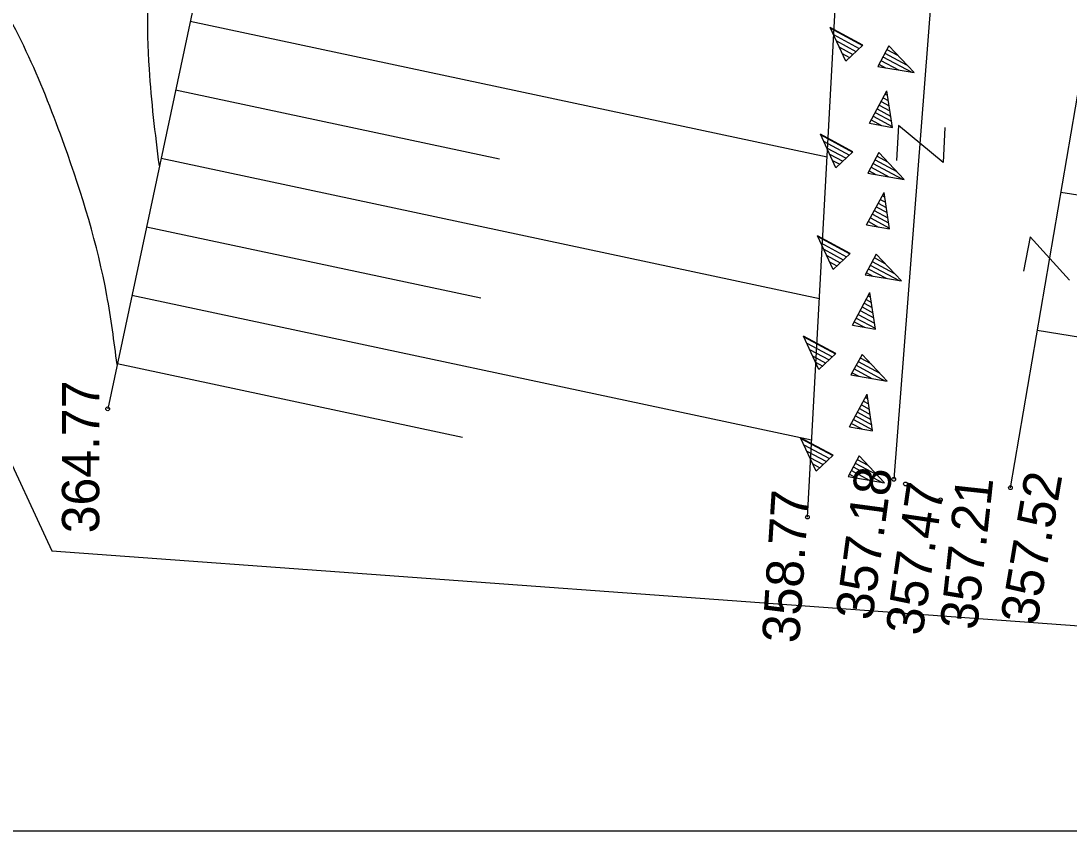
# Model space of a CAD drawing. Extents: x 4635329 to 4651863, y 5356628 to 5367582.
# Drawn here: x 4651179.57 to 4651202.03, y 5356627.73 to 5356645.09 of the extents above; entities that cross this region are included whole.
import ezdxf

# ---------------------------------------------------------------- set-up
doc = ezdxf.new("R2010")
doc.units = 0
for name, color, linetype in [('Level 1', 7, 'Continuous'), ('Level 13', 7, 'Continuous'), ('Level 44', 7, 'Continuous'), ('Level 45', 7, 'Continuous'), ('Level 46', 7, 'Continuous'), ('Level 48', 7, 'Continuous'), ('Level 49', 7, 'Continuous'), ('Level 50', 7, 'Continuous'), ('Level 53', 7, 'Continuous')]:
    doc.layers.add(name, color=color, linetype=linetype)

msp = doc.modelspace()

# ---------------------------------------------------------------- linework, layer by layer
at = {"layer": 'Level 1'}
for p, q in [((4651169.678, 5356656.408), (4651180.231, 5356633.731)), ((4651180.231, 5356633.731), (4651216.704, 5356631.078))]:
    msp.add_line(p, q, dxfattribs=at)
at = {"layer": 'Level 13'}
msp.add_lwpolyline([(4651092.18, 5356627.729), (4651092.18, 5356813.355), (4651331.195, 5356813.355), (4651331.195, 5356627.729)], close=True, dxfattribs=at)
at = {"layer": 'Level 44'}
for centre in [(4651181.425, 5356636.777), (4651198.275, 5356635.267), (4651198.525, 5356635.167), (4651200.775, 5356635.087), (4651199.275, 5356634.827), (4651196.425, 5356634.457)]:
    msp.add_circle(centre, 0.04, dxfattribs=at)
at = {"layer": 'Level 46'}
for points in [[(4651182.533, 5356641.982), (4651182.318, 5356644.059), (4651182.379, 5356646.848), (4651182.379, 5356648.849), (4651181.53, 5356650.244), (4651179.771, 5356652.002), (4651179.706, 5356652.031)], [(4651181.627, 5356637.725), (4651181.408, 5356639.209), (4651180.499, 5356642.422), (4651178.74, 5356646.121), (4651173.827, 5356650.062), (4651172.468, 5356650.413)]]:
    msp.add_spline(points, degree=3, dxfattribs=at)
at = {"layer": 'Level 48'}
for p, q in [((4651183.193, 5356645.083), (4651196.846, 5356642.176)), ((4651182.881, 5356643.616), (4651189.822, 5356642.138)), ((4651182.569, 5356642.149), (4651196.68, 5356639.144)), ((4651205.492, 5356640.832), (4651201.857, 5356641.413)), ((4651182.256, 5356640.681), (4651189.427, 5356639.155)), ((4651181.944, 5356639.214), (4651196.515, 5356636.112)), ((4651205.019, 5356637.869), (4651201.351, 5356638.456)), ((4651181.632, 5356637.747), (4651189.032, 5356636.172))]:
    msp.add_line(p, q, dxfattribs=at)
for points in [[(4651197.655, 5356677.577), (4651192.785, 5356671.627), (4651190.685, 5356664.357), (4651184.035, 5356649.037), (4651181.425, 5356636.777)], [(4651196.425, 5356634.457), (4651197.255, 5356649.677), (4651199.635, 5356666.497), (4651201.145, 5356666.267)]]:
    msp.add_lwpolyline(points, dxfattribs=at)
at = {"layer": 'Level 49'}
for p, q in [((4651197.61, 5356644.574), (4651196.913, 5356644.948)), ((4651197.246, 5356644.23), (4651196.913, 5356644.948)), ((4651196.919, 5356644.933), (4651197.602, 5356644.566)), ((4651196.983, 5356644.797), (4651197.533, 5356644.501)), ((4651197.046, 5356644.661), (4651197.464, 5356644.436)), ((4651197.61, 5356644.574), (4651197.246, 5356644.23)), ((4651197.109, 5356644.525), (4651197.395, 5356644.371)), ((4651197.172, 5356644.389), (4651197.326, 5356644.306)), ((4651198.168, 5356644.557), (4651197.932, 5356644.117)), ((4651198.085, 5356644.402), (4651198.55, 5356644.152)), ((4651198.128, 5356644.481), (4651198.355, 5356644.359)), ((4651198.711, 5356643.982), (4651198.168, 5356644.557)), ((4651197.235, 5356644.253), (4651197.257, 5356644.241)), ((4651197.957, 5356644.164), (4651198.1, 5356644.088)), ((4651198, 5356644.244), (4651198.38, 5356644.039)), ((4651198.042, 5356644.323), (4651198.661, 5356643.991)), ((4651197.932, 5356644.117), (4651198.711, 5356643.982)), ((4651197.752, 5356642.896), (4651198.126, 5356643.592)), ((4651198.089, 5356643.523), (4651198.14, 5356643.496)), ((4651198.245, 5356642.809), (4651198.126, 5356643.592)), ((4651197.962, 5356643.285), (4651198.191, 5356643.162)), ((4651198.004, 5356643.365), (4651198.175, 5356643.273)), ((4651198.047, 5356643.444), (4651198.158, 5356643.384)), ((4651197.834, 5356643.047), (4651198.243, 5356642.828)), ((4651197.876, 5356643.127), (4651198.225, 5356642.939)), ((4651197.919, 5356643.206), (4651198.208, 5356643.051)), ((4651197.752, 5356642.896), (4651198.245, 5356642.809)), ((4651197.791, 5356642.968), (4651198.011, 5356642.85)), ((4651197.399, 5356642.287), (4651196.702, 5356642.661)), ((4651197.035, 5356641.943), (4651196.702, 5356642.661)), ((4651196.709, 5356642.646), (4651197.392, 5356642.279)), ((4651196.772, 5356642.51), (4651197.323, 5356642.214)), ((4651196.835, 5356642.374), (4651197.254, 5356642.149)), ((4651196.898, 5356642.238), (4651197.185, 5356642.084)), ((4651196.961, 5356642.102), (4651197.116, 5356642.019)), ((4651197.399, 5356642.287), (4651197.035, 5356641.943)), ((4651197.958, 5356642.27), (4651197.721, 5356641.83)), ((4651197.874, 5356642.115), (4651198.34, 5356641.865)), ((4651197.917, 5356642.194), (4651198.144, 5356642.072)), ((4651198.5, 5356641.695), (4651197.958, 5356642.27)), ((4651197.025, 5356641.966), (4651197.047, 5356641.954)), ((4651197.747, 5356641.877), (4651197.889, 5356641.801)), ((4651197.789, 5356641.957), (4651198.17, 5356641.752)), ((4651197.832, 5356642.036), (4651198.45, 5356641.704)), ((4651197.721, 5356641.83), (4651198.5, 5356641.695)), ((4651197.692, 5356640.718), (4651198.066, 5356641.414)), ((4651197.986, 5356641.266), (4651198.097, 5356641.207)), ((4651198.029, 5356641.345), (4651198.08, 5356641.318)), ((4651198.185, 5356640.632), (4651198.066, 5356641.414)), ((4651197.858, 5356641.028), (4651198.147, 5356640.873)), ((4651197.901, 5356641.108), (4651198.131, 5356640.984)), ((4651197.944, 5356641.187), (4651198.115, 5356641.095)), ((4651197.731, 5356640.79), (4651197.95, 5356640.673)), ((4651197.773, 5356640.87), (4651198.182, 5356640.65)), ((4651197.816, 5356640.949), (4651198.165, 5356640.762)), ((4651197.692, 5356640.718), (4651198.185, 5356640.632)), ((4651197.338, 5356640.109), (4651196.642, 5356640.483)), ((4651196.975, 5356639.765), (4651196.642, 5356640.483)), ((4651196.648, 5356640.468), (4651197.331, 5356640.102)), ((4651196.712, 5356640.332), (4651197.262, 5356640.036)), ((4651196.775, 5356640.196), (4651197.193, 5356639.971)), ((4651197.338, 5356640.109), (4651196.975, 5356639.765)), ((4651197.897, 5356640.093), (4651197.661, 5356639.652)), ((4651198.44, 5356639.517), (4651197.897, 5356640.093)), ((4651196.838, 5356640.06), (4651197.124, 5356639.906)), ((4651196.901, 5356639.924), (4651197.055, 5356639.841)), ((4651197.771, 5356639.858), (4651198.39, 5356639.526)), ((4651197.814, 5356639.937), (4651198.279, 5356639.688)), ((4651197.857, 5356640.017), (4651198.084, 5356639.895)), ((4651196.964, 5356639.788), (4651196.986, 5356639.776)), ((4651197.661, 5356639.652), (4651198.44, 5356639.517)), ((4651197.686, 5356639.7), (4651197.829, 5356639.623)), ((4651197.729, 5356639.779), (4651198.109, 5356639.574)), ((4651197.389, 5356638.571), (4651197.763, 5356639.267)), ((4651197.726, 5356639.198), (4651197.777, 5356639.171)), ((4651197.882, 5356638.484), (4651197.763, 5356639.267)), ((4651197.598, 5356638.96), (4651197.828, 5356638.837)), ((4651197.641, 5356639.039), (4651197.812, 5356638.948)), ((4651197.684, 5356639.119), (4651197.795, 5356639.059)), ((4651197.513, 5356638.802), (4651197.862, 5356638.614)), ((4651197.556, 5356638.881), (4651197.845, 5356638.726)), ((4651197.389, 5356638.571), (4651197.882, 5356638.484)), ((4651197.428, 5356638.643), (4651197.647, 5356638.525)), ((4651197.471, 5356638.722), (4651197.879, 5356638.503)), ((4651197.036, 5356637.961), (4651196.339, 5356638.336)), ((4651196.672, 5356637.618), (4651196.339, 5356638.336)), ((4651196.346, 5356638.321), (4651197.029, 5356637.954)), ((4651196.409, 5356638.185), (4651196.96, 5356637.889)), ((4651196.472, 5356638.049), (4651196.891, 5356637.824)), ((4651196.535, 5356637.913), (4651196.822, 5356637.759)), ((4651197.036, 5356637.961), (4651196.672, 5356637.618)), ((4651197.595, 5356637.945), (4651197.358, 5356637.505)), ((4651197.554, 5356637.869), (4651197.781, 5356637.747)), ((4651198.137, 5356637.37), (4651197.595, 5356637.945)), ((4651196.598, 5356637.777), (4651196.752, 5356637.694)), ((4651196.661, 5356637.64), (4651196.683, 5356637.629)), ((4651197.426, 5356637.631), (4651197.807, 5356637.427)), ((4651197.469, 5356637.711), (4651198.087, 5356637.379)), ((4651197.511, 5356637.79), (4651197.977, 5356637.54)), ((4651197.358, 5356637.505), (4651198.137, 5356637.37)), ((4651197.384, 5356637.552), (4651197.526, 5356637.476)), ((4651197.329, 5356636.393), (4651197.703, 5356637.089)), ((4651197.623, 5356636.941), (4651197.734, 5356636.881)), ((4651197.666, 5356637.02), (4651197.717, 5356636.993)), ((4651197.822, 5356636.307), (4651197.703, 5356637.089)), ((4651197.538, 5356636.783), (4651197.768, 5356636.659)), ((4651197.581, 5356636.862), (4651197.751, 5356636.77)), ((4651197.41, 5356636.545), (4651197.819, 5356636.325)), ((4651197.453, 5356636.624), (4651197.802, 5356636.437)), ((4651197.495, 5356636.703), (4651197.784, 5356636.548)), ((4651197.329, 5356636.393), (4651197.822, 5356636.307)), ((4651197.368, 5356636.465), (4651197.587, 5356636.348)), ((4651196.975, 5356635.784), (4651196.279, 5356636.158)), ((4651196.611, 5356635.44), (4651196.279, 5356636.158)), ((4651196.285, 5356636.143), (4651196.968, 5356635.776)), ((4651196.348, 5356636.007), (4651196.899, 5356635.711)), ((4651196.412, 5356635.871), (4651196.83, 5356635.646)), ((4651196.475, 5356635.735), (4651196.761, 5356635.581)), ((4651196.538, 5356635.599), (4651196.692, 5356635.516)), ((4651196.975, 5356635.784), (4651196.611, 5356635.44)), ((4651197.534, 5356635.767), (4651197.298, 5356635.327)), ((4651197.451, 5356635.612), (4651197.916, 5356635.363)), ((4651197.494, 5356635.692), (4651197.721, 5356635.57)), ((4651198.077, 5356635.192), (4651197.534, 5356635.767)), ((4651196.601, 5356635.463), (4651196.623, 5356635.451)), ((4651197.323, 5356635.375), (4651197.466, 5356635.298)), ((4651197.366, 5356635.454), (4651197.746, 5356635.249)), ((4651197.408, 5356635.533), (4651198.027, 5356635.201)), ((4651197.298, 5356635.327), (4651198.077, 5356635.192))]:
    msp.add_line(p, q, dxfattribs=at)
at = {"layer": 'Level 50'}
for p, q in [((4651199.405, 5356649.827), (4651198.275, 5356635.267)), ((4651200.775, 5356635.087), (4651203.125, 5356648.827))]:
    msp.add_line(p, q, dxfattribs=at)
at = {"layer": 'Level 53'}
for p, q in [((4651198.373, 5356642.85), (4651198.337, 5356642.101)), ((4651199.336, 5356642.054), (4651198.373, 5356642.85)), ((4651199.372, 5356642.803), (4651199.336, 5356642.054)), ((4651201.201, 5356640.46), (4651201.058, 5356639.724)), ((4651202.039, 5356639.533), (4651201.201, 5356640.46))]:
    msp.add_line(p, q, dxfattribs=at)

# ---------------------------------------------------------------- texts
at = {"layer": 'Level 45'}
for s, rotation, p in [('364.77', 90, (4651181.245, 5356634.111)), ('357.18', 82.3239, (4651197.814, 5356632.224)), ('357.52', 80.3503, (4651201.343, 5356632.124)), ('357.47', 81.6529, (4651198.884, 5356631.896)), ('357.21', 83.7911, (4651200.057, 5356632.02)), ('358.77', 86.2906, (4651196.247, 5356631.742))]:
    msp.add_text(s, height=0.8, rotation=rotation, dxfattribs=at).set_placement(p)

doc.saveas('drawing.dxf')
